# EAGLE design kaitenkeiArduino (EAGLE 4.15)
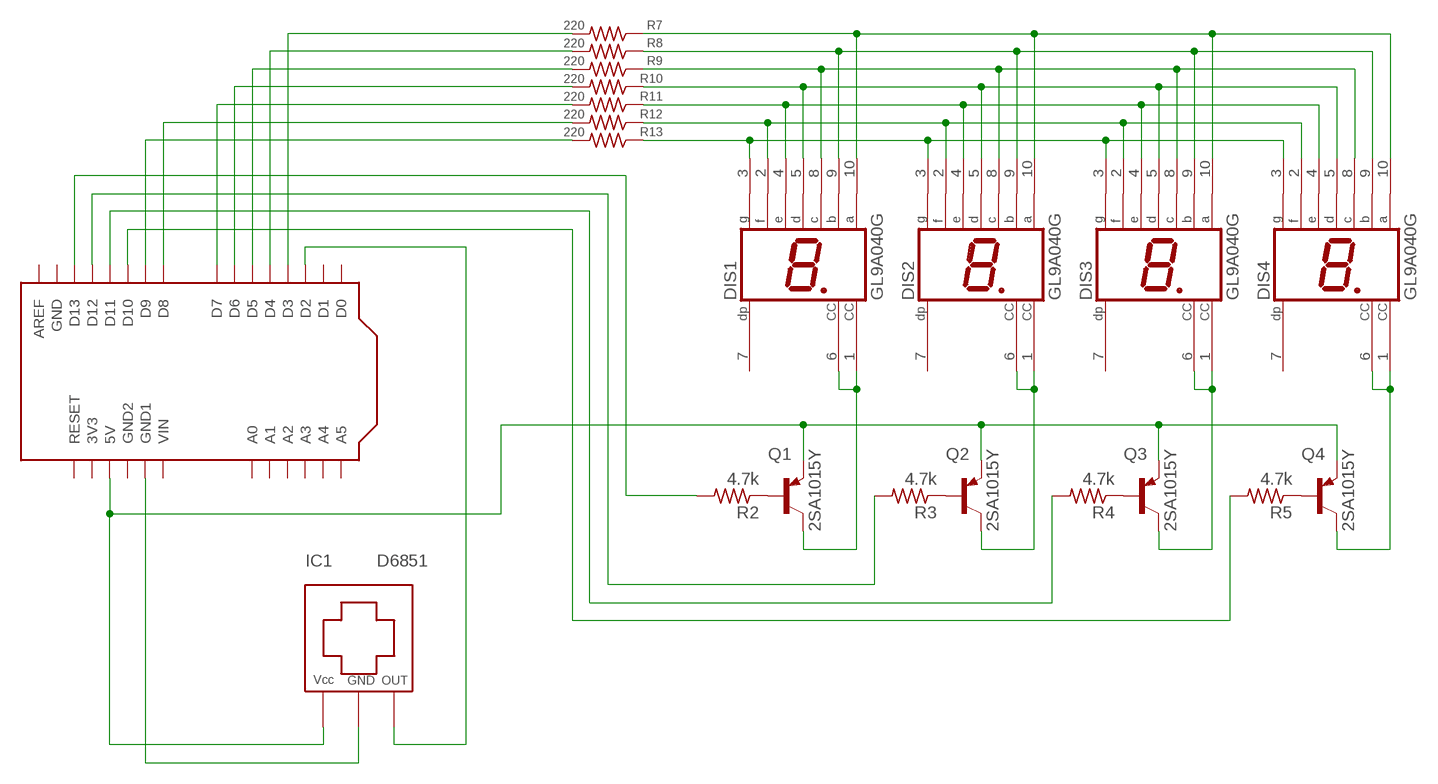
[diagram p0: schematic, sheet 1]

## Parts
DIS1  GL9A040G  HD-F103_OLMX  [HDSP-E_OLMX]
DIS2  GL9A040G  HD-F103_OLMX  [HDSP-E_OLMX]
DIS3  GL9A040G  HD-F103_OLMX  [HDSP-E_OLMX]
DIS4  GL9A040G  HD-F103_OLMX  [HDSP-E_OLMX]
IC1  D6851  HALL_IC  [HALL_IC]
Q1  2SA1015Y  BC636_OLMX  [TO92-BCE_OLMX]
Q2  2SA1015Y  BC636_OLMX  [TO92-BCE_OLMX]
Q3  2SA1015Y  BC636_OLMX  [TO92-BCE_OLMX]
Q4  2SA1015Y  BC636_OLMX  [TO92-BCE_OLMX]
R2  4.7k  R-US_0204/5_OLMX  [0204/5_OLMX]
R3  4.7k  R-US_0204/5_OLMX  [0204/5_OLMX]
R4  4.7k  R-US_0204/5_OLMX  [0204/5_OLMX]
R5  4.7k  R-US_0204/5_OLMX  [0204/5_OLMX]
R7  220  R-US_0204/5_OLMX  [0204/5_OLMX]
R8  220  R-US_0204/5_OLMX  [0204/5_OLMX]
R9  220  R-US_0204/5_OLMX  [0204/5_OLMX]
R10  220  R-US_0204/5_OLMX  [0204/5_OLMX]
R11  220  R-US_0204/5_OLMX  [0204/5_OLMX]
R12  220  R-US_0204/5_OLMX  [0204/5_OLMX]
R13  220  R-US_0204/5_OLMX  [0204/5_OLMX]
U$1  ARDUINOSHIELD  [ARDUINOSHIELD]

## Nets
GND: IC1.P$2(GND) U$1.GND1
N$1: DIS1.1(CC) DIS1.6(CC) Q1.C
N$2: R7.2 U$1.D3
N$3: R8.2 U$1.D4
N$4: R9.2 U$1.D5
N$5: R10.2 U$1.D6
N$6: R11.2 U$1.D7
N$7: R12.2 U$1.D8
N$8: R13.2 U$1.D9
N$9: IC1.P$1(VCC) Q1.E Q2.E Q3.E Q4.E U$1.5V
N$10: Q1.B R2.1
N$11: R2.2 U$1.D13
N$12: IC1.P$3(OUT) U$1.D2
N$13: DIS2.1(CC) DIS2.6(CC) Q2.C
N$14: DIS3.1(CC) DIS3.6(CC) Q3.C
N$15: DIS4.1(CC) DIS4.6(CC) Q4.C
N$17: Q2.B R3.1
N$18: R5.2 U$1.D10
N$19: R4.2 U$1.D11
N$20: R3.2 U$1.D12
N$21: Q3.B R4.1
N$22: Q4.B R5.1
N$31: DIS1.10(A) DIS2.10(A) DIS3.10(A) DIS4.10(A) R7.1
N$42: DIS1.9(B) DIS2.9(B) DIS3.9(B) DIS4.9(B) R8.1
N$44: DIS1.5(D) DIS2.5(D) DIS3.5(D) DIS4.5(D) R10.1
N$45: DIS1.2(F) DIS2.2(F) DIS3.2(F) DIS4.2(F) R12.1
N$46: DIS1.4(E) DIS2.4(E) DIS3.4(E) DIS4.4(E) R11.1
N$47: DIS1.3(G) DIS2.3(G) DIS3.3(G) DIS4.3(G) R13.1
N$55: DIS1.8(C) DIS2.8(C) DIS3.8(C) DIS4.8(C) R9.1
Unconnected: DIS1.7(DP) DIS2.7(DP) DIS3.7(DP) DIS4.7(DP) U$1.3V3 U$1.A0 U$1.A1 U$1.A2 U$1.A3 U$1.A4 U$1.A5 U$1.AREF U$1.D0 U$1.D1 U$1.GND U$1.GND2 U$1.RESET U$1.VIN

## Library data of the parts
DIS1-DIS4 = display-hp:HD-F103: LED DISPLAY 1-character 7 segment, decimal point right
IC1 = 001mylib:HALL_IC
Q1-Q4 = transistor-pnp:BC636*: PNP Transistror
R2-R5 R7-R13 = rcl:R-US_: RESISTOR, American symbol
U$1 = 001mylib:ARDUINOSHIELD

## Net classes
0 default: width 0.406 mm

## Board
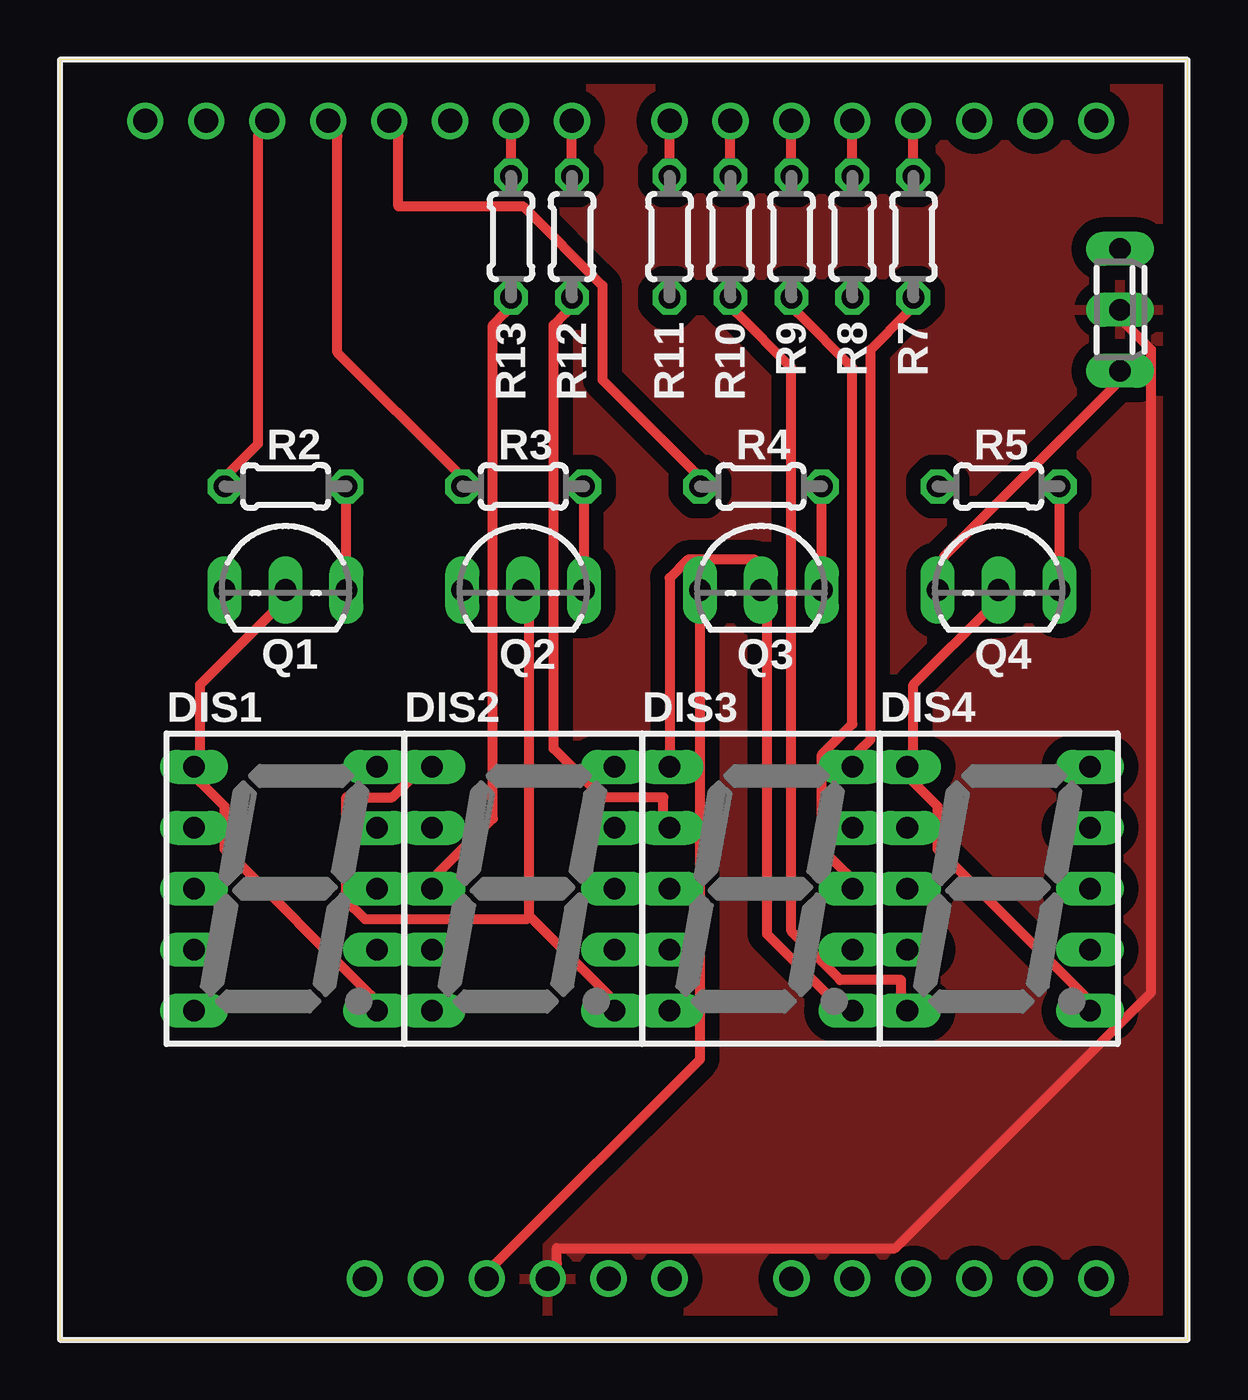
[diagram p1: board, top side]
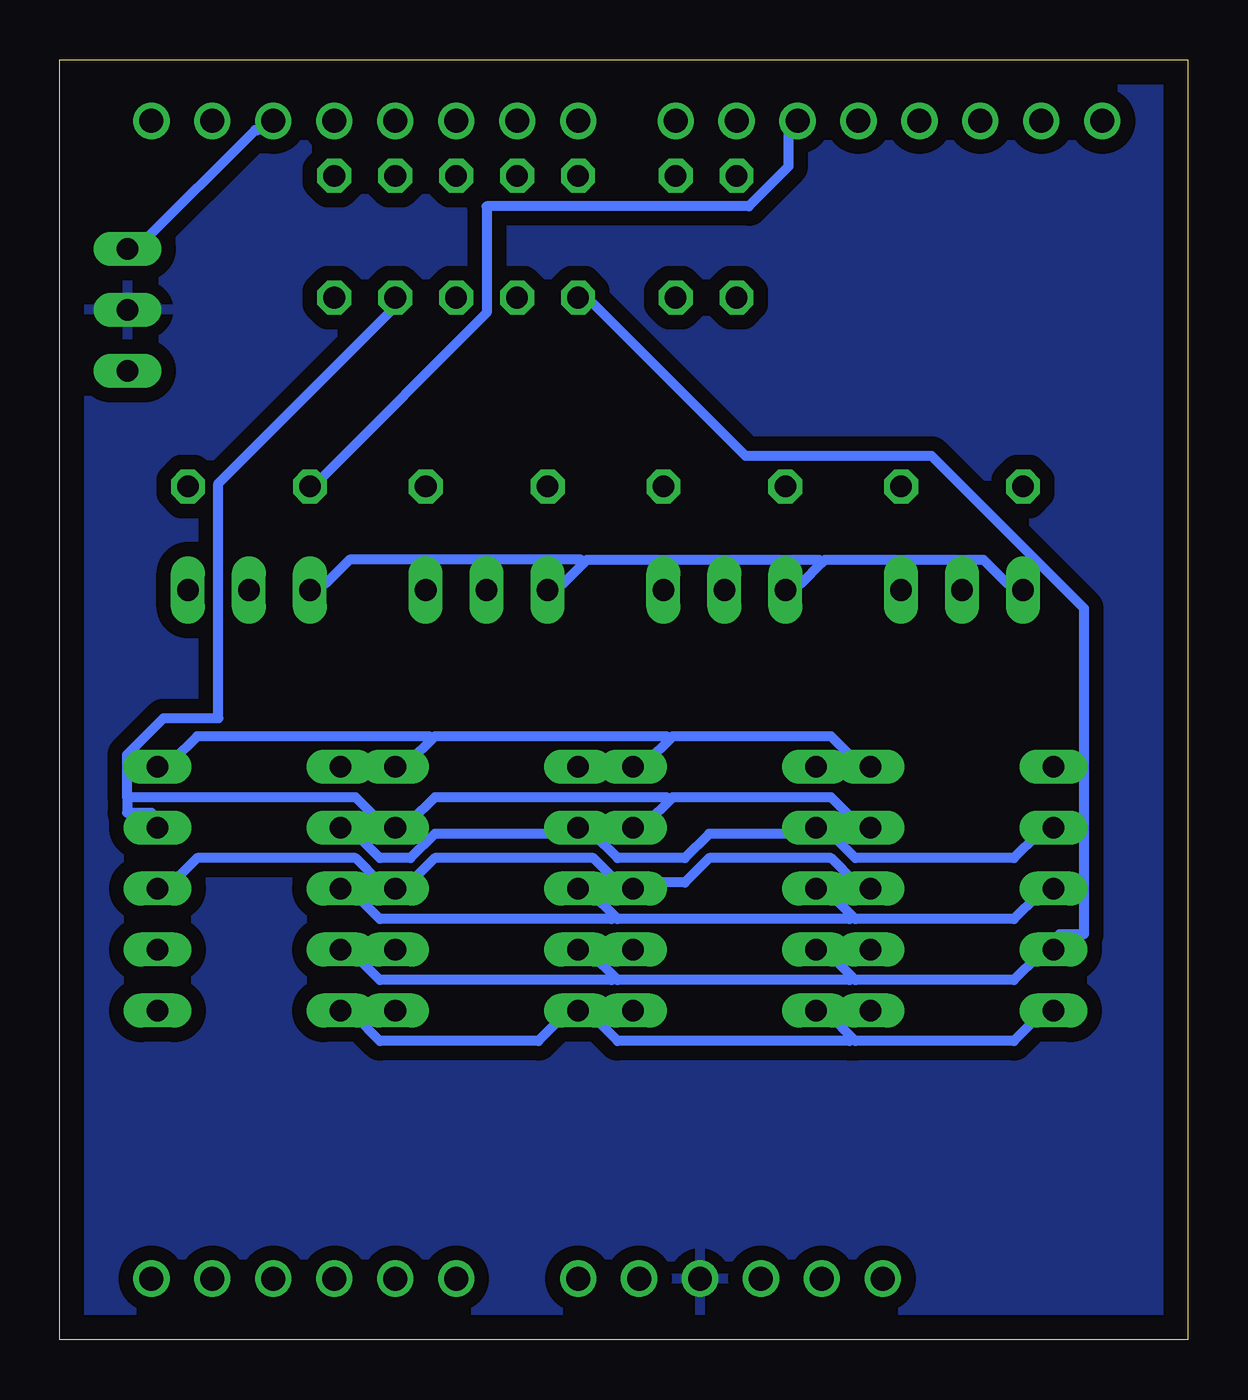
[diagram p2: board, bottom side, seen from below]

Size 46.99 x 53.34 mm. Coordinates in mm from the lower left corner, seen from the top.
Outline: 0,0 46.99,0 46.99,53.34 0,53.34 0,0
Copper layers (1*16): Top 0.035mm / dielectric 1.5mm / Bottom 0.035mm
Design rules "default": minimum track width 10mil, minimum drill 24mil, track to track 12mil, track to pad 12mil, pad to pad 12mil, via to via 12mil, smd to smd 12mil, copper to edge 40mil, drill to drill 8mil, minimum pad ring 10mil, minimum via ring 8mil, stop-mask expansion 4mil, vias tented up to drill 0mil, thermal gap 20mil

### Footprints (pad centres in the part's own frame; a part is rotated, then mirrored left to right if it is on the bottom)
HDSP-E_OLMX = drill 0.9 long: 1 -3.81,5.08; 2 -3.81,2.54; 3 -3.81,0; 4 -3.81,-2.54; 5 -3.81,-5.08; 6 3.81,-5.08; 7 3.81,-2.54; 8 3.81,0; 9 3.81,2.54; 10 3.81,5.08
HALL_IC = drill 0.9 long: P$1 -2.54,0.02; P$2 0,0.02; P$3 2.54,0.02
TO92-BCE_OLMX = drill 0.9 long: B 2.54,0; C 0,0; E -2.54,0
0204/5_OLMX = drill 0.9 octagon: 1 -2.54,0; 2 2.54,0
ARDUINOSHIELD = drill 1 round: 3V3 35.56,2.54; 5V 38.1,2.54; A0 50.8,2.54; A1 53.34,2.54; A2 55.88,2.54; A3 58.42,2.54; A4 60.96,2.54; A5 63.5,2.54; AREF 23.876,50.8; D0 63.5,50.8; D1 60.96,50.8; D2 58.42,50.8; D3 55.88,50.8; D4 53.34,50.8; D5 50.8,50.8; D6 48.26,50.8; D7 45.72,50.8; D8 41.656,50.8; D9 39.116,50.8; D10 36.576,50.8; D11 34.036,50.8; D12 31.496,50.8; D13 28.956,50.8; GND 26.416,50.8; GND1 40.64,2.54; GND2 43.18,2.54; RESET 33.02,2.54; VIN 45.72,2.54

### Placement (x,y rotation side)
DIS1  9.4,18.8 0 top
DIS2  19.3,18.8 0 top
DIS3  29.21,18.8 0 top
DIS4  39.12,18.8 0 top
IC1  44.2,42.93 90 top
Q1  9.4,31.24 0 top
Q2  19.3,31.24 0 top
Q3  29.21,31.24 0 top
Q4  39.12,31.24 0 top
R2  9.4,35.56 180 top
R3  19.3,35.56 180 top
R4  29.21,35.56 180 top
R5  39.12,35.56 180 top
R7  35.56,45.97 90 top
R8  33.02,45.97 90 top
R9  30.48,45.97 90 top
R10  27.94,45.97 90 top
R11  25.4,45.97 90 top
R12  21.34,45.97 90 top
R13  18.8,45.97 90 top
U$1  -20.32,0 0 top

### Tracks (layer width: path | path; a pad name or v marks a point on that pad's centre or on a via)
GND
  Top 0.406: IC1.P$2 44.45,42.29 45.47,41.27 45.47,14.48 34.8,3.81 20.7,3.81 20.7,3.17 U$1.GND1
  pour Top (isolate 0.61): 0,58.42 50.8,58.42 50.8,-3.81 0,-3.81
  pour Bottom (isolate 0.61): -2.54,55.88 49.53,55.88 49.53,-2.54 -2.54,-2.54
N$1
  Top 0.406: DIS1.6 12.95,14.35 6.86,20.45 6.86,22.23 5.84,23.24 DIS1.1 5.84,24.51 5.84,27.3 9.14,30.61 Q1.C
N$2
  Top 0.406: R7.2 U$1.D3
N$3
  Top 0.406: R8.2 U$1.D4
N$4
  Top 0.406: R9.2 U$1.D5
N$5
  Top 0.406: R10.2 U$1.D6
N$6
  Top 0.406: R11.2 U$1.D7
N$7
  Top 0.406: R12.2 U$1.D8
N$8
  Top 0.406: R13.2 U$1.D9
N$9
  Top 0.406: IC1.P$1 43.94,39.75 36.83,32.64 36.83,31.88 Q4.E | U$1.5V 18.16,3.17 26.67,11.68 Q3.E
  Bottom 0.406: 15.24,32.38 16.13,31.5 Q2.E | 15.24,32.38 15.11,32.51 8.51,32.51 7.49,31.5 Q1.E | 25.15,32.38 25.02,32.51 15.37,32.51 15.24,32.38 | 25.15,32.38 26.04,31.5 Q3.E | Q4.E 35.94,31.5 34.92,32.51 25.27,32.51 25.15,32.38
N$10
  Top 0.406: Q1.B R2.1
N$11
  Top 0.406: R2.2 7.11,36.2 8.26,37.34 8.26,50.16 U$1.D13
N$12
  Bottom 0.406: IC1.P$3 43.56,45.72 38.86,50.42 38.73,50.42 U$1.D2
N$13
  Top 0.406: 19.56,17.65 22.86,14.35 DIS2.6 | 19.56,17.65 19.56,30.61 Q2.C | DIS2.1 14.86,23.62 13.84,22.61 11.94,22.61 11.94,18.29 12.7,17.53 19.43,17.53 19.56,17.65
N$14
  Top 0.406: DIS3.6 32.38,13.97 29.46,16.89 29.46,30.61 Q3.C 28.96,31.88 28.96,32.51 26.16,32.51 25.4,31.75 DIS3.1
N$15
  Top 0.406: DIS4.6 42.67,14.35 36.58,20.45 36.58,22.23 35.56,23.24 DIS4.1 35.56,24.51 35.56,27.3 38.86,30.61 Q4.C
N$17
  Top 0.406: Q2.B R3.1
N$18
  Bottom 0.406: R5.2 36.07,35.94 29.21,42.8 29.21,47.24 18.29,47.24 16.64,48.9 16.64,50.16 U$1.D10
N$19
  Top 0.406: R4.2 26.42,36.2 22.61,40.01 22.61,43.94 19.3,47.24 14.1,47.24 14.1,50.16 U$1.D11
N$20
  Top 0.406: R3.2 16.51,36.2 11.56,41.15 11.56,50.16 U$1.D12
N$21
  Top 0.406: Q3.B R4.1
N$22
  Top 0.406: Q4.B R5.1
N$31
  Top 0.406: R7.1 35.31,42.8 33.78,41.27 33.78,25.02 33.27,24.51 DIS3.10
  Bottom 0.406: 21.59,25.02 22.48,24.13 DIS2.10 | 21.59,25.02 21.46,25.15 14.86,25.15 13.84,24.13 DIS1.10 | 31.5,25.02 31.37,25.15 21.72,25.15 21.59,25.02 | 31.5,25.02 32.38,24.13 DIS3.10 | DIS4.10 42.29,24.13 41.27,25.15 31.62,25.15 31.5,25.02
N$42
  Bottom 0.406: 21.59,22.48 22.48,21.59 DIS2.9 | 21.59,22.48 21.46,22.61 14.86,22.61 13.84,21.59 DIS1.9 | 21.59,22.48 21.72,22.61 31.37,22.61 32.38,21.59 DIS3.9 33.66,21.59 34.67,22.61 44.2,22.61 | 44.2,22.61 44.2,21.97 43.18,21.97 DIS4.9 | 44.2,22.61 44.2,24.38 42.67,25.91 40.39,25.91 40.39,35.69 33.27,42.8 R8.1
N$44
  Top 0.406: R10.1 28.19,42.8 30.48,40.51 30.48,17.02 32.51,14.99 35.05,14.99 35.05,14.35 DIS4.5
  Bottom 0.406: 13.97,12.57 14.86,13.46 DIS2.5 | 13.97,12.57 13.84,12.45 7.24,12.45 6.22,13.46 DIS1.5 | 13.97,12.57 14.1,12.45 23.75,12.45 24.77,13.46 DIS3.5 26.04,13.46 27.05,12.45 33.66,12.45 34.67,13.46 DIS4.5
N$45
  Top 0.406: R12.1 21.08,42.8 20.57,42.29 20.57,24.64 22.61,22.61 25.15,22.61 25.15,21.97 DIS3.2
  Bottom 0.406: DIS1.2 6.22,21.08 7.24,20.07 13.84,20.07 14.86,21.08 DIS2.2 16.13,21.08 19.94,21.08 20.95,20.07 23.75,20.07 24.77,21.08 DIS3.2 26.04,21.08 31.37,21.08 32.38,20.07 33.66,20.07 34.67,21.08 DIS4.2
N$46
  Bottom 0.406: 13.97,15.11 14.86,16 DIS2.4 | 13.97,15.11 13.84,14.99 7.24,14.99 6.22,16 DIS1.4 5.33,16.89 4.32,16.89 4.32,30.48 10.67,36.83 18.41,36.83 24.77,43.18 R11.1 | 23.88,15.11 23.75,14.99 14.1,14.99 13.97,15.11 | 23.88,15.11 24.77,16 DIS3.4 | DIS4.4 34.67,16 33.66,14.99 24,14.99 23.88,15.11
N$47
  Top 0.406: R13.1 18.54,42.8 18.03,42.29 18.03,21.72 15.75,19.43 DIS2.3
  Bottom 0.406: 13.97,17.65 14.86,18.54 DIS2.3 | 13.97,17.65 13.84,17.53 7.24,17.53 6.22,18.54 DIS1.3 | 23.88,17.65 23.75,17.53 14.1,17.53 13.97,17.65 | 23.88,17.65 24.77,18.54 DIS3.3 | DIS4.3 34.67,18.54 33.66,17.53 24,17.53 23.88,17.65
N$55
  Top 0.406: R9.1 30.73,42.8 33.02,40.51 33.02,25.65 31.75,24.38 31.75,20.45 32.77,19.43 DIS3.8
  Bottom 0.406: DIS1.8 13.84,19.05 14.86,20.07 19.94,20.07 20.95,19.05 22.48,19.05 DIS2.8 23.75,19.05 24.77,20.07 31.37,20.07 32.38,19.05 DIS3.8 33.66,19.05 34.67,20.07 41.27,20.07 42.29,19.05 DIS4.8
